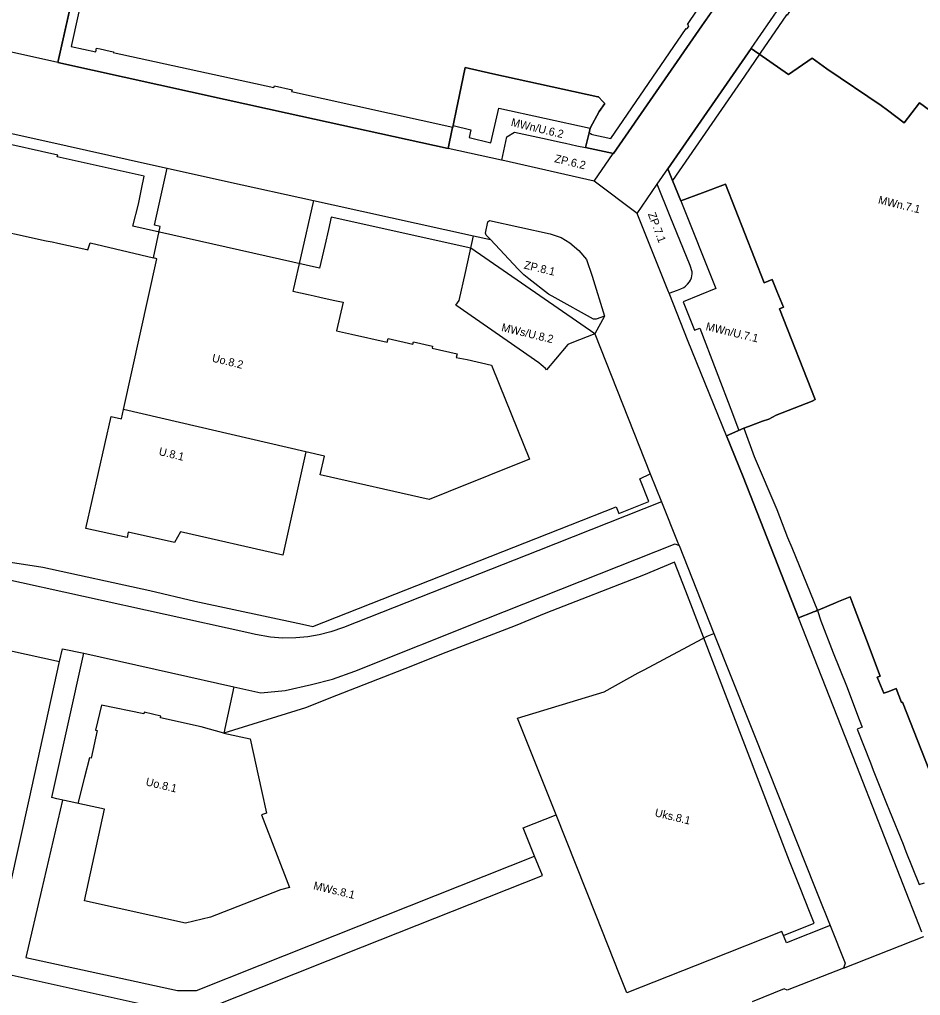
# Model space of a CAD drawing. Extents: x 7429686 to 7432896, y 5547954 to 5550600.
# Drawn here: x 7431331.5 to 7431781.4, y 5549169.6 to 5549657.1 of the extents above; entities that cross this region are included whole.
import ezdxf

# ---------------------------------------------------------------- set-up
doc = ezdxf.new("R2010")
doc.units = 0
for name, color, linetype in [('linie rozgraniczające', 7, 'Continuous'), ('obowiązująca linia zabudowy', 7, 'Continuous'), ('oznaczenia przeznaczeń', 7, 'Continuous')]:
    doc.layers.add(name, color=color, linetype=linetype)

msp = doc.modelspace()

# ---------------------------------------------------------------- linework, layer by layer
at = {"layer": 'linie rozgraniczające'}
for p, q in [((7431672.28, 5549654.05), (7431714.41, 5549714.66)), ((7431359.15, 5549673.6), (7431350.69, 5549635.72)), ((7431628.07, 5549590.29), (7431672.28, 5549654.05)), ((7431696.82, 5549642.68), (7431655.28, 5549582.48)), ((7431715.54, 5549629.72), (7431696.82, 5549642.68)), ((7431727.32, 5549637.84), (7431715.54, 5549629.72)), ((7431550.18, 5549614.7), (7431554, 5549633.11)), ((7431620.28, 5549618.5), (7431620.69, 5549618.47)), ((7431620.69, 5549618.47), (7431622.81, 5549616.26)), ((7431623.74, 5549615.2), (7431620.91, 5549611.15)), ((7431622.81, 5549616.26), (7431623.74, 5549615.2)), ((7431620.91, 5549611.15), (7431616.52, 5549602.8)), ((7431545.52, 5549592.7), (7431547.58, 5549602.5)), ((7431547.58, 5549602.5), (7431547.83, 5549603.37)), ((7431614.1, 5549593.2), (7431628.07, 5549590.29)), ((7431684.08, 5549574.94), (7431703.4, 5549525.55)), ((7431703.4, 5549525.55), (7431707.36, 5549527.22)), ((7431712.98, 5549513.36), (7431710.94, 5549512.56)), ((7431710.94, 5549512.56), (7431728.88, 5549467.26)), ((7431684.47, 5549449.23), (7431692.8, 5549428.71)), ((7431692.8, 5549428.71), (7431720.47, 5549358.29)), ((7431740.49, 5549366.39), (7431746.22, 5549368.67)), ((7431746.22, 5549368.67), (7431748.23, 5549363.4)), ((7431761.27, 5549329.18), (7431759.74, 5549328.57))]:
    msp.add_line(p, q, dxfattribs=at)
for points in [[(7431350.69, 5549635.72), (7431359.15, 5549673.6), (7431300.13, 5549695.97), (7431299.66, 5549696.15), (7431304.47, 5549715.98), (7431303.72, 5549721.28), (7431319.02, 5549792.1), (7431330.89, 5549804.16), (7431332.59, 5549812.04), (7431332.2, 5549812.2), (7431339.7, 5549846.45), (7431340.14, 5549846.42), (7431341.93, 5549854.71), (7431345.63, 5549857.59), (7431346.28, 5549858.1)], [(7431714.41, 5549714.66), (7431672.28, 5549654.05), (7431628.07, 5549590.29)], [(7431696.82, 5549642.68), (7431711.33, 5549663.7)], [(7431350.69, 5549635.72), (7431275.64, 5549652.27)], [(7431655.28, 5549582.48), (7431696.82, 5549642.68)], [(7431696.82, 5549642.68), (7431715.54, 5549629.72)], [(7431350.69, 5549635.72), (7431434.13, 5549617.24), (7431465.19, 5549610.36), (7431545.52, 5549592.7)], [(7431545.52, 5549592.7), (7431465.19, 5549610.36), (7431434.13, 5549617.24), (7431350.69, 5549635.72)], [(7431715.54, 5549629.72), (7431727.32, 5549637.84), (7431734.7, 5549632.58), (7431761.71, 5549614.21), (7431764.98, 5549611.87), (7431773.29, 5549605.48), (7431780.86, 5549615.54), (7431795.29, 5549605.07), (7431815.03, 5549633.4)], [(7431764.98, 5549611.87), (7431761.71, 5549614.21), (7431734.7, 5549632.58), (7431727.32, 5549637.84)], [(7431622.81, 5549616.26), (7431620.69, 5549618.47), (7431620.28, 5549618.5), (7431567.86, 5549630.05), (7431554, 5549633.11), (7431550.18, 5549614.7), (7431549.93, 5549613.16), (7431547.98, 5549604.22), (7431547.83, 5549603.37), (7431547.58, 5549602.5), (7431545.52, 5549592.7)], [(7431554, 5549633.11), (7431567.86, 5549630.05), (7431620.28, 5549618.5)], [(7431547.83, 5549603.37), (7431547.98, 5549604.22), (7431549.93, 5549613.16), (7431550.18, 5549614.7)], [(7431614.1, 5549593.2), (7431616.01, 5549600.47), (7431616.52, 5549602.8), (7431620.91, 5549611.15), (7431623.74, 5549615.2), (7431622.81, 5549616.26)], [(7431795.29, 5549605.07), (7431780.86, 5549615.54), (7431773.29, 5549605.48), (7431764.98, 5549611.87)], [(7431274.89, 5549611.78), (7431345.61, 5549596.13)], [(7431574.85, 5549598.48), (7431578.74, 5549600.81)], [(7431578.74, 5549600.81), (7431592.72, 5549597.79)], [(7431616.52, 5549602.8), (7431616.01, 5549600.47), (7431614.1, 5549593.2)], [(7431345.61, 5549596.13), (7431395.47, 5549585.05)], [(7431572.32, 5549586.81), (7431574.85, 5549598.48)], [(7431592.72, 5549597.79), (7431602.41, 5549595.68)], [(7431602.41, 5549595.68), (7431604.11, 5549595.4)], [(7431604.11, 5549595.4), (7431609.84, 5549594.09)], [(7431572.22, 5549586.83), (7431545.52, 5549592.7)], [(7431609.84, 5549594.09), (7431614.1, 5549593.2)], [(7431628.07, 5549590.29), (7431614.1, 5549593.2)], [(7431618.46, 5549576.35), (7431628, 5549590.2)], [(7431628, 5549590.2), (7431628.07, 5549590.29)], [(7431395.47, 5549585.05), (7431405.15, 5549582.84)], [(7431572.32, 5549586.81), (7431572.22, 5549586.83)], [(7431618.46, 5549576.35), (7431572.32, 5549586.81)], [(7431398.88, 5549554.44), (7431405.15, 5549582.84)], [(7431405.15, 5549582.84), (7431435.8, 5549576.07)], [(7431649.99, 5549574.82), (7431655.28, 5549582.48)], [(7431655.28, 5549582.48), (7431657.59, 5549576.7), (7431661.67, 5549566.54)], [(7431684.47, 5549449.23), (7431693.27, 5549452.93), (7431695.51, 5549453.87), (7431702.5, 5549456.46), (7431705.66, 5549457.57), (7431709.39, 5549459.53), (7431727.31, 5549466.56), (7431728.88, 5549467.26), (7431710.94, 5549512.56), (7431712.98, 5549513.36), (7431709.68, 5549521.49), (7431707.36, 5549527.22), (7431703.4, 5549525.55), (7431684.08, 5549574.94), (7431672.56, 5549570.62), (7431661.67, 5549566.54), (7431657.59, 5549576.7), (7431655.28, 5549582.48)], [(7431435.8, 5549576.07), (7431478.31, 5549566.7)], [(7431639.9, 5549560.2), (7431618.46, 5549576.35)], [(7431639.9, 5549560.2), (7431649.99, 5549574.82)], [(7431656.47, 5549558.8), (7431649.99, 5549574.82)], [(7431661.67, 5549566.54), (7431672.56, 5549570.62), (7431684.08, 5549574.94)], [(7431478.31, 5549566.7), (7431471.86, 5549538.07)], [(7431478.31, 5549566.7), (7431488.11, 5549564.61)], [(7431488.11, 5549564.61), (7431558.2, 5549549.09)], [(7431564.19, 5549550.39), (7431565.4, 5549555.99)], [(7431565.4, 5549555.99), (7431566.14, 5549556.67)], [(7431566.14, 5549556.67), (7431596.43, 5549550.14)], [(7431651.93, 5549530.3), (7431639.9, 5549560.2)], [(7431666.41, 5549534.22), (7431656.47, 5549558.8)], [(7431311.49, 5549553.94), (7431344.79, 5549546.64)], [(7431398.35, 5549538.02), (7431401.79, 5549553.7)], [(7431401.79, 5549553.7), (7431398.88, 5549554.44)], [(7431344.79, 5549546.64), (7431347.72, 5549546)], [(7431554.18, 5549530.79), (7431558.2, 5549549.09)], [(7431558.2, 5549549.09), (7431566.74, 5549547.2)], [(7431564.6, 5549549.42), (7431564.19, 5549550.39)], [(7431566.74, 5549547.2), (7431564.6, 5549549.42)], [(7431580.5, 5549532.45), (7431566.74, 5549547.2)], [(7431596.43, 5549550.14), (7431602.04, 5549548.19)], [(7431602.04, 5549548.19), (7431606.36, 5549545.63)], [(7431347.72, 5549546), (7431350.64, 5549545.36)], [(7431350.64, 5549545.36), (7431365.15, 5549542.17)], [(7431365.15, 5549542.17), (7431365.59, 5549542.08)], [(7431365.59, 5549542.08), (7431366.71, 5549545.66)], [(7431366.71, 5549545.66), (7431398.35, 5549538.02)], [(7431606.36, 5549545.63), (7431610.79, 5549541.81)], [(7431610.79, 5549541.81), (7431614.62, 5549537.26)], [(7431383.47, 5549462.36), (7431400.12, 5549537.54)], [(7431400.12, 5549537.54), (7431398.35, 5549538.02)], [(7431471.86, 5549538.07), (7431468.26, 5549522.85)], [(7431614.62, 5549537.26), (7431617.51, 5549528.91)], [(7431583.3, 5549529.62), (7431580.5, 5549532.45)], [(7431667.43, 5549531.09), (7431666.41, 5549534.22)], [(7431551.09, 5549516.76), (7431554.18, 5549530.79)], [(7431585.87, 5549527.62), (7431583.3, 5549529.62)], [(7431595.7, 5549519.99), (7431585.87, 5549527.62)], [(7431617.51, 5549528.91), (7431623.65, 5549508.97)], [(7431655.65, 5549521.07), (7431651.93, 5549530.3)], [(7431666.03, 5549526.15), (7431666.51, 5549526.93)], [(7431666.51, 5549526.93), (7431667.05, 5549528.13)], [(7431667.05, 5549528.13), (7431667.42, 5549530.09)], [(7431667.42, 5549530.09), (7431667.43, 5549531.09)], [(7431707.36, 5549527.22), (7431709.68, 5549521.49), (7431712.98, 5549513.36)], [(7431468.26, 5549522.85), (7431467.92, 5549521.41)], [(7431655.88, 5549520.48), (7431660.03, 5549521.98)], [(7431660.03, 5549521.98), (7431661.76, 5549522.65)], [(7431661.76, 5549522.65), (7431663.15, 5549523.31)], [(7431663.15, 5549523.31), (7431664.08, 5549523.96)], [(7431664.08, 5549523.96), (7431665.08, 5549524.93)], [(7431665.08, 5549524.93), (7431666.03, 5549526.15)], [(7431467.92, 5549521.41), (7431475.56, 5549519.84)], [(7431475.56, 5549519.84), (7431478.69, 5549519.13)], [(7431478.69, 5549519.13), (7431481.53, 5549518.5)], [(7431481.53, 5549518.5), (7431488.18, 5549516.98)], [(7431488.18, 5549516.98), (7431493.05, 5549515.88)], [(7431598.96, 5549518.11), (7431595.7, 5549519.99)], [(7431618.1, 5549507.52), (7431598.96, 5549518.11)], [(7431655.88, 5549520.48), (7431655.65, 5549521.07)], [(7431665.37, 5549496.28), (7431655.88, 5549520.48)], [(7431493.05, 5549515.88), (7431489.82, 5549501.64)], [(7431549.42, 5549514.43), (7431551.09, 5549516.76)], [(7431590.76, 5549485.58), (7431549.42, 5549514.43)], [(7431619.38, 5549507.53), (7431618.1, 5549507.52)], [(7431623.65, 5549508.97), (7431618.82, 5549500.12)], [(7431623.65, 5549508.97), (7431619.38, 5549507.53)], [(7431489.82, 5549501.64), (7431497.34, 5549499.95)], [(7431497.34, 5549499.95), (7431515.14, 5549495.94)], [(7431515.14, 5549495.94), (7431515.65, 5549497.82)], [(7431515.65, 5549497.82), (7431527.93, 5549495.02)], [(7431618.82, 5549500.12), (7431607.26, 5549495.55)], [(7431618.82, 5549500.12), (7431646.49, 5549430.14)], [(7431527.93, 5549495.02), (7431528.18, 5549496.11)], [(7431528.18, 5549496.11), (7431537.72, 5549493.99)], [(7431537.72, 5549493.99), (7431537.47, 5549492.94)], [(7431537.47, 5549492.94), (7431549.99, 5549490.16)], [(7431605.35, 5549494.78), (7431599.18, 5549487.48)], [(7431607.26, 5549495.55), (7431605.35, 5549494.78)], [(7431684.47, 5549449.23), (7431665.37, 5549496.28)], [(7431549.99, 5549490.16), (7431549.61, 5549488.36)], [(7431549.61, 5549488.36), (7431554.97, 5549487.28)], [(7431554.97, 5549487.28), (7431567.17, 5549484.41)], [(7431567.17, 5549484.41), (7431571.06, 5549474.94)], [(7431592, 5549484.65), (7431590.76, 5549485.58)], [(7431593.02, 5549483.8), (7431592, 5549484.65)], [(7431594.07, 5549482.85), (7431593.02, 5549483.8)], [(7431594.63, 5549482.08), (7431594.07, 5549482.85)], [(7431599.18, 5549487.48), (7431594.63, 5549482.08)], [(7431571.06, 5549474.94), (7431586.23, 5549437.5)], [(7431728.88, 5549467.26), (7431727.31, 5549466.56), (7431709.39, 5549459.53), (7431705.66, 5549457.57), (7431702.5, 5549456.46), (7431695.51, 5549453.87)], [(7431364.57, 5549402.94), (7431377.22, 5549458.88)], [(7431377.22, 5549458.88), (7431382.45, 5549457.74)], [(7431382.45, 5549457.74), (7431383.47, 5549462.36)], [(7431474.39, 5549441.16), (7431383.47, 5549462.36)], [(7431695.51, 5549453.87), (7431693.27, 5549452.93), (7431684.47, 5549449.23)], [(7431720.47, 5549358.29), (7431692.8, 5549428.71), (7431684.47, 5549449.23)], [(7431474.39, 5549441.16), (7431463.03, 5549389.54)], [(7431483.72, 5549438.98), (7431474.39, 5549441.16)], [(7431481.64, 5549429.69), (7431483.72, 5549438.98)], [(7431586.23, 5549437.5), (7431545.53, 5549421.18)], [(7431536.07, 5549417.42), (7431481.64, 5549429.69)], [(7431646.49, 5549430.14), (7431652, 5549416.19)], [(7431545.53, 5549421.18), (7431536.07, 5549417.42)], [(7431652, 5549416.19), (7431590.27, 5549391.73)], [(7431652, 5549416.19), (7431660.29, 5549395.72)], [(7431385.17, 5549398.44), (7431364.57, 5549402.94)], [(7431385.77, 5549401.11), (7431385.17, 5549398.44)], [(7431408.91, 5549395.84), (7431385.77, 5549401.11)], [(7431411.95, 5549401.22), (7431408.91, 5549395.84)], [(7431463.03, 5549389.54), (7431411.95, 5549401.22)], [(7431564.1, 5549357.59), (7431658.97, 5549395.2)], [(7431658.97, 5549395.2), (7431660.82, 5549394.38)], [(7431660.29, 5549395.72), (7431660.82, 5549394.38)], [(7431590.27, 5549391.73), (7431537.61, 5549370.92)], [(7431660.82, 5549394.38), (7431678.15, 5549350.36)], [(7431444.94, 5549350.86), (7431322.62, 5549377.89)], [(7431537.61, 5549370.92), (7431493.35, 5549353.37)], [(7431800.94, 5549243.7), (7431772.38, 5549316.19), (7431771.9, 5549315.98), (7431769.26, 5549322.91), (7431765.54, 5549321.5), (7431763.07, 5549320.56), (7431759.74, 5549328.57), (7431761.27, 5549329.18), (7431754.39, 5549347.23), (7431748.23, 5549363.4), (7431746.22, 5549368.67), (7431740.49, 5549366.39), (7431739.01, 5549365.66), (7431730.31, 5549362.12), (7431729.91, 5549361.94), (7431729.73, 5549361.87), (7431729.15, 5549361.63), (7431728.57, 5549361.39), (7431727.98, 5549361.16), (7431727.4, 5549360.92), (7431720.47, 5549358.29)], [(7431729.91, 5549361.94), (7431730.31, 5549362.12), (7431739.01, 5549365.66), (7431740.49, 5549366.39)], [(7431221.89, 5549364.84), (7431351.47, 5549336.38)], [(7431720.47, 5549358.29), (7431727.4, 5549360.92), (7431727.98, 5549361.16), (7431728.57, 5549361.39), (7431729.15, 5549361.63), (7431729.73, 5549361.87), (7431729.91, 5549361.94)], [(7431748.23, 5549363.4), (7431754.39, 5549347.23), (7431761.27, 5549329.18)], [(7431498.91, 5549331.56), (7431564.1, 5549357.59)], [(7431749.63, 5549284.08), (7431720.47, 5549358.29)], [(7431487.01, 5549351.23), (7431481.09, 5549349.76)], [(7431493.35, 5549353.37), (7431487.01, 5549351.23)], [(7431449.41, 5549349.87), (7431444.94, 5549350.86)], [(7431456.76, 5549348.65), (7431449.41, 5549349.87)], [(7431462.89, 5549348.11), (7431456.76, 5549348.65)], [(7431469.53, 5549348.22), (7431462.89, 5549348.11)], [(7431475.52, 5549348.8), (7431469.53, 5549348.22)], [(7431481.09, 5549349.76), (7431475.52, 5549348.8)], [(7431643.49, 5549332.32), (7431674.88, 5549349.16)], [(7431674.88, 5549349.16), (7431678.15, 5549350.36)], [(7431678.15, 5549350.36), (7431705.31, 5549282.28)], [(7431351.47, 5549336.38), (7431352.87, 5549342.74)], [(7431352.87, 5549342.74), (7431363.57, 5549340.52)], [(7431347.63, 5549268.42), (7431363.57, 5549340.52)], [(7431363.57, 5549340.52), (7431407.45, 5549330.7)], [(7431336.22, 5549267.3), (7431351.47, 5549336.38)], [(7431487.83, 5549327.57), (7431498.91, 5549331.56)], [(7431640.46, 5549330.81), (7431643.49, 5549332.32)], [(7431407.45, 5549330.7), (7431438.55, 5549323.83)], [(7431477.32, 5549324.97), (7431487.83, 5549327.57)], [(7431623.5, 5549321.25), (7431640.46, 5549330.81)], [(7431759.74, 5549328.57), (7431763.07, 5549320.56), (7431765.54, 5549321.5), (7431769.26, 5549322.91), (7431771.9, 5549315.98), (7431772.38, 5549316.19), (7431800.94, 5549243.7)], [(7431438.55, 5549323.83), (7431433.54, 5549300.7)], [(7431438.55, 5549323.83), (7431451.92, 5549320.83)], [(7431451.92, 5549320.83), (7431464.17, 5549321.97)], [(7431464.17, 5549321.97), (7431477.32, 5549324.97)], [(7431580.21, 5549308.08), (7431623.5, 5549321.25)], [(7431599.41, 5549259.76), (7431580.21, 5549308.08)], [(7431433.54, 5549300.7), (7431446.71, 5549297.81)], [(7431446.71, 5549297.81), (7431452.31, 5549272.01)], [(7431782.16, 5549201.26), (7431749.63, 5549284.08)], [(7431705.31, 5549282.28), (7431728.88, 5549223.19)], [(7431350.11, 5549267.87), (7431347.63, 5549268.42)], [(7431452.31, 5549272.01), (7431454.76, 5549260.73)], [(7431317.19, 5549181.59), (7431336.22, 5549267.3)], [(7431373.97, 5549262.58), (7431350.11, 5549267.87)], [(7431363.92, 5549216.86), (7431373.97, 5549262.58)], [(7431454.76, 5549260.73), (7431452.39, 5549259.83)], [(7431452.39, 5549259.83), (7431466.32, 5549223.49)], [(7431582.94, 5549253.31), (7431599.41, 5549259.76)], [(7431619.42, 5549209.49), (7431599.41, 5549259.76)], [(7431583.95, 5549250.8), (7431582.94, 5549253.31)], [(7431588.67, 5549239.12), (7431583.95, 5549250.8)], [(7431592.57, 5549229.46), (7431588.67, 5549239.12)], [(7431502.84, 5549193.96), (7431592.57, 5549229.46)], [(7431461.84, 5549222.34), (7431450.34, 5549217.83)], [(7431466.32, 5549223.49), (7431461.84, 5549222.34)], [(7431728.88, 5549223.19), (7431730.19, 5549219.91)], [(7431730.19, 5549219.91), (7431736.34, 5549204.5)], [(7431414.45, 5549205.74), (7431363.92, 5549216.86)], [(7431450.34, 5549217.83), (7431426.86, 5549208.64)], [(7431426.86, 5549208.64), (7431414.45, 5549205.74)], [(7431631.15, 5549180.04), (7431619.42, 5549209.49)], [(7431712.21, 5549201.62), (7431676.05, 5549187.3)], [(7431714.48, 5549195.88), (7431712.21, 5549201.62)], [(7431736.34, 5549204.5), (7431714.48, 5549195.88)], [(7431736.34, 5549204.5), (7431743.83, 5549185.7)], [(7431742.92, 5549183.29), (7431783.03, 5549199.05)], [(7431452.13, 5549173.77), (7431502.84, 5549193.96)], [(7431676.05, 5549187.3), (7431634.78, 5549170.96)], [(7431743.83, 5549185.7), (7431742.92, 5549183.29)], [(7431742.92, 5549183.29), (7431714.78, 5549172.22)], [(7431417.65, 5549159.61), (7431327.86, 5549179.5)], [(7431634.78, 5549170.96), (7431631.15, 5549180.04)], [(7431418.23, 5549160.27), (7431452.13, 5549173.77)], [(7431713.37, 5549172.84), (7431697.41, 5549166.43)], [(7431714.78, 5549172.22), (7431713.37, 5549172.84)]]:
    msp.add_lwpolyline(points, dxfattribs=at)
at = {"layer": 'obowiązująca linia zabudowy'}
msp.add_line((7431481.3, 5549532.87), (7431388.08, 5549553.89), dxfattribs=at)
for points in [[(7431626.8, 5549597.76), (7431664.36, 5549652.68), (7431664.8, 5549652.45), (7431665.74, 5549653.73), (7431665.43, 5549654), (7431665.61, 5549654.29), (7431664.99, 5549654.7), (7431669.82, 5549661.81), (7431670.71, 5549661.35), (7431671.43, 5549662.38), (7431671.11, 5549662.66), (7431695.3, 5549697.49), (7431694.49, 5549698.23), (7431696.94, 5549701.47), (7431697.66, 5549700.93), (7431705.8, 5549712.45), (7431696.2, 5549719.48), (7431695.58, 5549718.78), (7431688.71, 5549723.66), (7431689.69, 5549725.42), (7431634.7, 5549763.77), (7431615.39, 5549776.81), (7431584.64, 5549797.95), (7431581.96, 5549794.13)], [(7431773.4, 5549744.6), (7431759.38, 5549724.04), (7431759.07, 5549724.28), (7431746.83, 5549706.73), (7431741.13, 5549698.11), (7431715.67, 5549660.69), (7431714.76, 5549659.38), (7431714.47, 5549659.55), (7431701.27, 5549640.26), (7431693.49, 5549628.9), (7431657.59, 5549576.7)], [(7431364.29, 5549675.54), (7431357.35, 5549643.62), (7431369.53, 5549641.02), (7431369.91, 5549642.91), (7431371.7, 5549642.54), (7431376.73, 5549641.39), (7431378.43, 5549641), (7431378.33, 5549640.71), (7431458.52, 5549623.11), (7431458.79, 5549624.09), (7431467.6, 5549622.03), (7431467.34, 5549621.13), (7431547.83, 5549603.37), (7431547.98, 5549604.22), (7431556.85, 5549602.1), (7431556.05, 5549598.21), (7431566.81, 5549595.61), (7431570.88, 5549612.83), (7431616.52, 5549602.8), (7431616.01, 5549600.47), (7431616.81, 5549600.24), (7431616.75, 5549599.92), (7431626.8, 5549597.76)], [(7431388.08, 5549553.89), (7431390.82, 5549564.96), (7431392.34, 5549572.47), (7431393.73, 5549578.86), (7431350.33, 5549588.51), (7431350.59, 5549589.36), (7431288.19, 5549603.31), (7431287.93, 5549602.46), (7431274.25, 5549605.45)], [(7431661.67, 5549566.54), (7431679.21, 5549522.81)], [(7431618.82, 5549500.12), (7431556.83, 5549542.86), (7431487.08, 5549558.4), (7431485.71, 5549552.22), (7431483.91, 5549544.21), (7431481.3, 5549532.87)], [(7431679.21, 5549522.81), (7431662.92, 5549516.15), (7431668.57, 5549502), (7431671.19, 5549503.02)], [(7431671.19, 5549503.02), (7431687.52, 5549460.38), (7431690.78, 5549451.88)], [(7431693.27, 5549452.93), (7431698.38, 5549438.88), (7431709.64, 5549412.3), (7431714.98, 5549398.44), (7431717.15, 5549393.39), (7431729.91, 5549361.94), (7431731.67, 5549356.78), (7431737.83, 5549340.73), (7431744.51, 5549324.24), (7431750.78, 5549307.43), (7431752.23, 5549303.56)], [(7431629.5, 5549413.74), (7431630.84, 5549410.4), (7431645.78, 5549416.35), (7431641.32, 5549427.65), (7431646.49, 5549430.14)], [(7431477.93, 5549353.91), (7431541.75, 5549379.01), (7431555.48, 5549384.52), (7431606.63, 5549404.71), (7431629.5, 5549413.74)], [(7431313.77, 5549387.98), (7431343.19, 5549383.59), (7431396.54, 5549371.89), (7431419.03, 5549366.65), (7431472.72, 5549355.03), (7431477.93, 5549353.91)], [(7431713.03, 5549199.55), (7431728.38, 5549205.66), (7431726.04, 5549211.56), (7431721.37, 5549223.28), (7431716.05, 5549236.63), (7431664.29, 5549371.56), (7431658.59, 5549385.97), (7431643.17, 5549379.62), (7431594.39, 5549360.63), (7431579.02, 5549354.24), (7431542.26, 5549340.07), (7431526.82, 5549333.95), (7431489.78, 5549319.37), (7431474.34, 5549313.24), (7431433.54, 5549300.7)], [(7431372.38, 5549314.68), (7431369.4, 5549302.09), (7431370.3, 5549301.9), (7431367.3, 5549288.17), (7431366.36, 5549288.37), (7431363.88, 5549278.61), (7431360.56, 5549265.55)], [(7431433.54, 5549300.7), (7431422.15, 5549303.78), (7431401.85, 5549308.27), (7431401.98, 5549309.05), (7431393.66, 5549311.04), (7431393.48, 5549310.21), (7431372.38, 5549314.68)], [(7431752.23, 5549303.56), (7431749.78, 5549302.56), (7431756.38, 5549285.79), (7431757.78, 5549282.13), (7431764.38, 5549265.55), (7431765.99, 5549261.9), (7431772.7, 5549245.18), (7431774.05, 5549241.57), (7431780.76, 5549224.96), (7431783.38, 5549225.92)], [(7431352.95, 5549267.24), (7431342.49, 5549222.19), (7431334.68, 5549188.61)], [(7431334.68, 5549188.61), (7431410.34, 5549172.03), (7431419.87, 5549172.11), (7431451.68, 5549184.74), (7431588.67, 5549239.12)]]:
    msp.add_lwpolyline(points, dxfattribs=at)

# ---------------------------------------------------------------- texts
at = {"layer": 'oznaczenia przeznaczeń'}
for s, rotation, p in [('MWn/U.6.2', 346.4891, (7431576.64, 5549604.06)), ('ZP.6.2', 346.4891, (7431598.37, 5549585.94)), ('MWn.7.1', 346.4891, (7431760, 5549565.28)), ('ZP.7.1', 290.5009, (7431645.22, 5549559.98)), ('ZP.8.1', 346.4891, (7431583.12, 5549532.8)), ('MWs/U.8.2', 346.4891, (7431571.86, 5549501.58)), ('MWn/U.7.1', 346.4891, (7431673.92, 5549502.06)), ('Uo.8.2', 346.4891, (7431427.32, 5549486.28)), ('U.8.1', 346.4891, (7431400.76, 5549439.62)), ('Uo.8.1', 346.4891, (7431394.25, 5549274.62)), ('Uks.8.1', 346.4891, (7431648.46, 5549259.15)), ('MWs.8.1', 346.4891, (7431477.96, 5549222.71))]:
    msp.add_text(s, height=4, rotation=rotation, dxfattribs=at).set_placement(p)

doc.saveas('drawing.dxf')
